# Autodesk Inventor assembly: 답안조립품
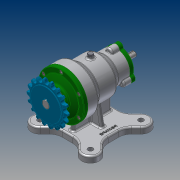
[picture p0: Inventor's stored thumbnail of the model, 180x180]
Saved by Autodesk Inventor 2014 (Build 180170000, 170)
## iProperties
Created: 2017-03
Part Number: 답안조립품
Document SubType Name: Assembly
Designer: Administrator
Author: Administrator
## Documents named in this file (14)
- C:\Users\Administrator\Desktop\470308V1008\답안조립품.iam
- C:\Users\Administrator\Desktop\470308V1008\뒤커버.ipt
- C:\Users\Administrator\Desktop\470308V1008\베어링-6200.ipt
- C:\Users\Administrator\Desktop\470308V1008\베어링-6203.ipt
- C:\Users\Administrator\Desktop\470308V1008\본체.ipt
- C:\Users\Administrator\Desktop\470308V1008\볼트 M4 x 12.ipt
- C:\Users\Administrator\Desktop\470308V1008\볼트 M5 x 10.ipt
- 볼트 M5 x 10.ipt
- C:\Users\Administrator\Desktop\470308V1008\스프로킷.ipt
- C:\Users\Administrator\Desktop\470308V1008\앞커버.ipt
- C:\Users\Administrator\Desktop\470308V1008\오일 실 10 20 7.ipt
- C:\Users\Administrator\Desktop\470308V1008\오일 실 17 30 8.ipt
- C:\Users\Administrator\Desktop\470308V1008\축.ipt
- C:\Users\Administrator\Desktop\470308V1008\키5x5.ipt
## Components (9 placed, 1 different names)
1. ISO 4762 M4 x 12:1 — 각도:4
2. ISO 4762 M4 x 12:3 — 각도:6
3. ISO 4762 M4 x 12:4 — 각도:5
4. ISO 4762 M4 x 12:2 — 각도:7
5. ISO 4762 M4 x 12:5
6. ISO 4762 M4 x 12:6
7. ISO 4762 M4 x 12:7
8. ISO 4762 M4 x 12:8
9. ISO 4762 M4 x 12:9
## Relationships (4: Angle 4)
- 각도:4 [Angle]: ISO 4762 M4 x 12:1
- 각도:5 [Angle]: ISO 4762 M4 x 12:4
- 각도:6 [Angle]: ISO 4762 M4 x 12:3
- 각도:7 [Angle]: ISO 4762 M4 x 12:2
